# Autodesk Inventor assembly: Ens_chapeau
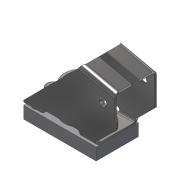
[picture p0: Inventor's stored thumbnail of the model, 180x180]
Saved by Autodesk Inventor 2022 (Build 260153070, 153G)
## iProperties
Created: 2018-06
Part Number: Ens_chapeau
Material: Générique
Document SubType Name: Assembly
Designer: Fabian Perrée
Mass: 105.136 g
Surface Area: 173.547 cm^2
Volume: 19.7524 cm^3
Density: 5.32267 g/cm^3
Author: Fabian Perrée
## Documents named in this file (5)
- C:\Users\Fabian\Google Drive\01_Giup\01_Clients\07_ENI\Manuscrit\Fichiers_exercice\Chapitre_06\Exercice_jeu_de_composant_en_contact\Composants\Ens_chapeau\Ens_chapeau.iam
- C:\Users\Fabian\Google Drive\01_Giup\01_Clients\07_ENI\Manuscrit\Fichiers_exercice\Capteur\Ens_chapeau\Composants\Chapeau_capteur.ipt
- C:\Users\Fabian\Google Drive\01_Giup\01_Clients\07_ENI\Manuscrit\Fichiers_exercice\Capteur\Ens_chapeau\Composants\Bille_18.ipt
- C:\Users\Fabian\Google Drive\01_Giup\01_Clients\07_ENI\Manuscrit\Fichiers_exercice\Capteur\Ens_levier\Composants\Etrier_tole.ipt
- C:\Users\Fabian\Google Drive\01_Giup\01_Clients\07_ENI\Manuscrit\Fichiers_exercice\CC\fr-FR\ISO 4762(2)\ISO 4762 - M5 x 8ISO.ipt
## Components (5 placed, 4 different names)
1. Etrier_tole:1 — Logement:3, Logement:4
2. Chapeau_capteur:1 — Logement:3, Logement:4
3. Bille_18:1
4. ISO 4762 M5 x 8:1
5. ISO 4762 M5 x 8:2
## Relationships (2: Insert 2)
- Logement:3 [Insert]: Etrier_tole:1 ↔ Chapeau_capteur:1
- Logement:4 [Insert]: Etrier_tole:1 ↔ Chapeau_capteur:1
